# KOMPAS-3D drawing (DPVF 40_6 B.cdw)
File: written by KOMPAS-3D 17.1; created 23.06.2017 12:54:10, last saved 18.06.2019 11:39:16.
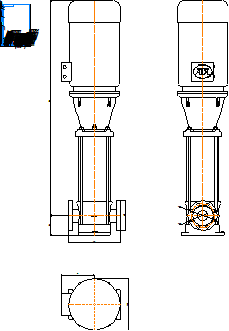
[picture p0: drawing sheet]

Sheet 1: A4, portrait

Title block, sheet 1: name: DPVF 40_6 B; material: Внимание! Данный продукт является объектом авторского права ООО «Торговый Дом АДЛ». / Запрещается изменение, копирование, распространение / (в том числе путем копирования на другие сайты и ресурсы в Интернете) / или любое иное использование информации и объектов без предварительного / согласия правообладателя (ООО «Торговый Дом АДЛ»).; scale: 1:1; sheets: 1; organisation: ООО "Торговый дом АДЛ"; sheet format: A4; stored path: C:\Клочков АВ\Насосы\DP PAMS\DPVF 40\Компас 2d\DPVF 40_6 B.cdw

Views: Спереди 1
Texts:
  Клочков АВ
  ООО АДЛ ГРУПП
Dimensions and other numbers on the sheet: 365; 234; 360; 209,6; 1505,5; 140; 168,1; 76,2; 1:1; 1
